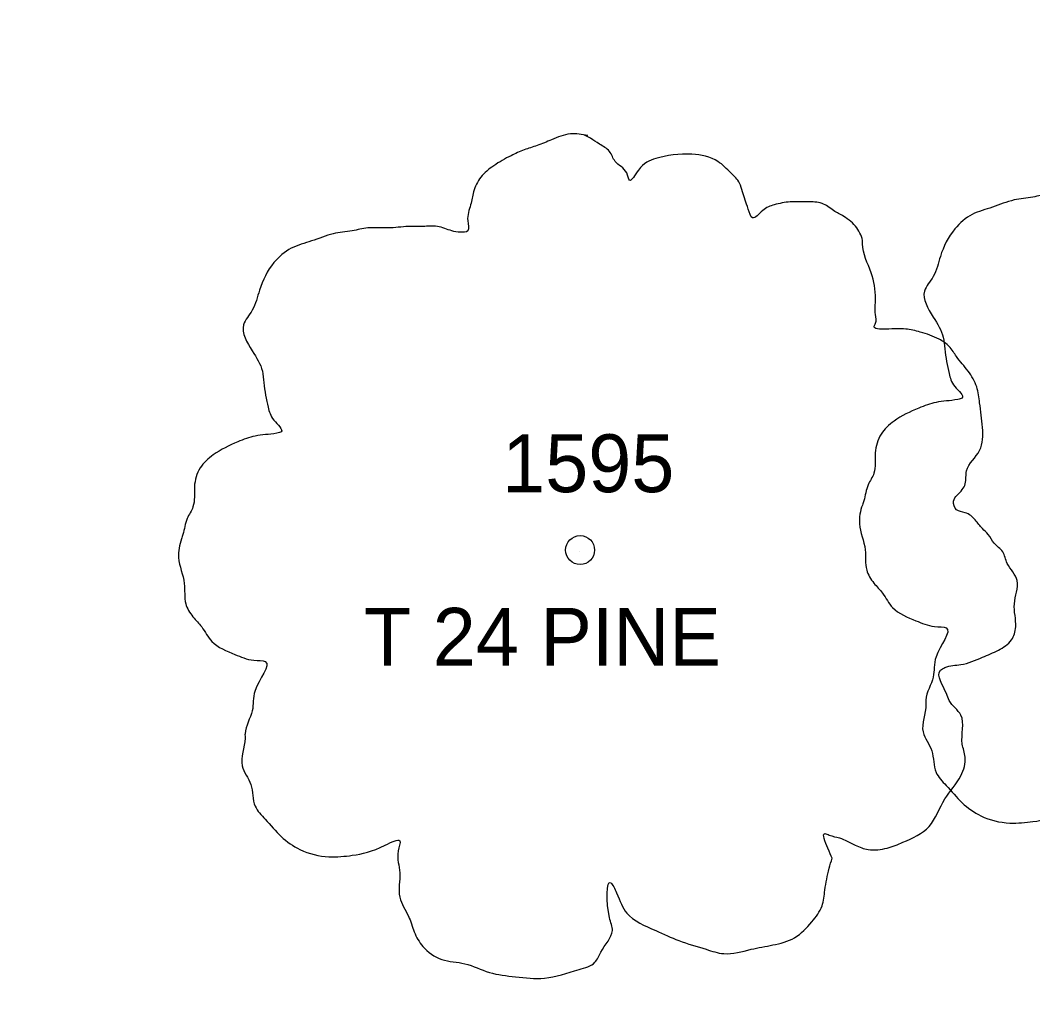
# Model space of a CAD drawing. Extents: x 1964982 to 1970452, y 1116335 to 1119906.
# Drawn here: x 1966640.09 to 1966657.58, y 1117477.19 to 1117494.07 of the extents above; entities that cross this region are included whole.
import ezdxf

# ---------------------------------------------------------------- set-up
doc = ezdxf.new("R2010")
doc.units = 0
for name, color, linetype in [('RD_EX_VEG', 7, 'Continuous'), ('RD_EX_VEG_txCode', 7, 'Continuous'), ('RD_HC_CL_Rel', 7, 'Continuous'), ('RD_HC_Data', 7, 'Continuous'), ('RD_PD_Final_TrvlWay', 7, 'Continuous')]:
    doc.layers.add(name, color=color, linetype=linetype)

msp = doc.modelspace()

# ---------------------------------------------------------------- linework, layer by layer
at = {"layer": 'RD_EX_VEG'}
for centre, radius in [((1966649.762, 1117484.912), 0.25), ((1966649.762, 1117484.912), 0.25), ((1966649.749, 1117484.893), 0.0001), ((1966649.749, 1117484.893), 0.0001)]:
    msp.add_circle(centre, radius, dxfattribs=at)
for points in [[(1966661.661, 1117492.662), (1966661.361, 1117492.687), (1966661.036, 1117492.587), (1966660.786, 1117492.487), (1966660.561, 1117492.412), (1966660.336, 1117492.312), (1966660.036, 1117492.138), (1966659.811, 1117491.938), (1966659.686, 1117491.688), (1966659.636, 1117491.463), (1966659.586, 1117491.188), (1966659.586, 1117491.013), (1966659.462, 1117490.988), (1966659.312, 1117491.013), (1966659.062, 1117491.088), (1966658.812, 1117491.088), (1966658.562, 1117491.088), (1966658.212, 1117491.063), (1966657.862, 1117491.063), (1966657.587, 1117491.013), (1966657.262, 1117490.963), (1966656.888, 1117490.838), (1966656.538, 1117490.713), (1966656.238, 1117490.463), (1966655.988, 1117489.989), (1966655.863, 1117489.639), (1966655.713, 1117489.389), (1966655.863, 1117488.939), (1966656.038, 1117488.589), (1966656.063, 1117488.389), (1966656.138, 1117487.964), (1966656.238, 1117487.74), (1966656.363, 1117487.54), (1966656.288, 1117487.515), (1966655.913, 1117487.465), (1966655.613, 1117487.365), (1966655.188, 1117487.14), (1966654.963, 1117486.915), (1966654.863, 1117486.59), (1966654.839, 1117486.24), (1966654.739, 1117486.04), (1966654.664, 1117485.765), (1966654.639, 1117485.69), (1966654.589, 1117485.366), (1966654.689, 1117484.916), (1966654.714, 1117484.566), (1966654.839, 1117484.341), (1966654.988, 1117484.166), (1966655.163, 1117483.916), (1966655.563, 1117483.691), (1966655.888, 1117483.591), (1966656.088, 1117483.566), (1966655.913, 1117483.067), (1966655.863, 1117482.717), (1966655.738, 1117482.317), (1966655.738, 1117482.242), (1966655.688, 1117481.767), (1966655.838, 1117481.442), (1966655.913, 1117481.067), (1966656.088, 1117480.843), (1966656.363, 1117480.543), (1966656.688, 1117480.318), (1966657.188, 1117480.193), (1966657.587, 1117480.218), (1966658.162, 1117480.393), (1966658.412, 1117480.468), (1966658.387, 1117480.293), (1966658.412, 1117479.918), (1966658.412, 1117479.493), (1966658.562, 1117479.168), (1966658.662, 1117478.893), (1966658.812, 1117478.643), (1966659.137, 1117478.419), (1966659.536, 1117478.344), (1966659.961, 1117478.194), (1966660.411, 1117478.119), (1966660.911, 1117478.094), (1966661.511, 1117478.244), (1966661.785, 1117478.369), (1966661.885, 1117478.544), (1966662.085, 1117478.918), (1966662.035, 1117479.143), (1966662.06, 1117479.743), (1966662.16, 1117479.568), (1966662.335, 1117479.218), (1966662.835, 1117478.918), (1966663.235, 1117478.743), (1966663.71, 1117478.593), (1966664.01, 1117478.519), (1966664.484, 1117478.593), (1966664.859, 1117478.668), (1966665.234, 1117478.793), (1966665.534, 1117479.068), (1966665.709, 1117479.343), (1966665.759, 1117479.618), (1966665.834, 1117479.993), (1966665.884, 1117480.168)], [(1966661.661, 1117492.662), (1966661.361, 1117492.687), (1966661.036, 1117492.587), (1966660.786, 1117492.487), (1966660.561, 1117492.412), (1966660.336, 1117492.312), (1966660.036, 1117492.138), (1966659.811, 1117491.938), (1966659.686, 1117491.688), (1966659.636, 1117491.463), (1966659.586, 1117491.188), (1966659.586, 1117491.013), (1966659.462, 1117490.988), (1966659.312, 1117491.013), (1966659.062, 1117491.088), (1966658.812, 1117491.088), (1966658.562, 1117491.088), (1966658.212, 1117491.063), (1966657.862, 1117491.063), (1966657.587, 1117491.013), (1966657.262, 1117490.963), (1966656.888, 1117490.838), (1966656.538, 1117490.713), (1966656.238, 1117490.463), (1966655.988, 1117489.989), (1966655.863, 1117489.639), (1966655.713, 1117489.389), (1966655.863, 1117488.939), (1966656.038, 1117488.589), (1966656.063, 1117488.389), (1966656.138, 1117487.964), (1966656.238, 1117487.74), (1966656.363, 1117487.54), (1966656.288, 1117487.515), (1966655.913, 1117487.465), (1966655.613, 1117487.365), (1966655.188, 1117487.14), (1966654.963, 1117486.915), (1966654.863, 1117486.59), (1966654.839, 1117486.24), (1966654.739, 1117486.04), (1966654.664, 1117485.765), (1966654.639, 1117485.69), (1966654.589, 1117485.366), (1966654.689, 1117484.916), (1966654.714, 1117484.566), (1966654.839, 1117484.341), (1966654.988, 1117484.166), (1966655.163, 1117483.916), (1966655.563, 1117483.691), (1966655.888, 1117483.591), (1966656.088, 1117483.566), (1966655.913, 1117483.067), (1966655.863, 1117482.717), (1966655.738, 1117482.317), (1966655.738, 1117482.242), (1966655.688, 1117481.767), (1966655.838, 1117481.442), (1966655.913, 1117481.067), (1966656.088, 1117480.843), (1966656.363, 1117480.543), (1966656.688, 1117480.318), (1966657.188, 1117480.193), (1966657.587, 1117480.218), (1966658.162, 1117480.393), (1966658.412, 1117480.468), (1966658.387, 1117480.293), (1966658.412, 1117479.918), (1966658.412, 1117479.493), (1966658.562, 1117479.168), (1966658.662, 1117478.893), (1966658.812, 1117478.643), (1966659.137, 1117478.419), (1966659.536, 1117478.344), (1966659.961, 1117478.194), (1966660.411, 1117478.119), (1966660.911, 1117478.094), (1966661.511, 1117478.244), (1966661.785, 1117478.369), (1966661.885, 1117478.544), (1966662.085, 1117478.918), (1966662.035, 1117479.143), (1966662.06, 1117479.743), (1966662.16, 1117479.568), (1966662.335, 1117479.218), (1966662.835, 1117478.918), (1966663.235, 1117478.743), (1966663.71, 1117478.593), (1966664.01, 1117478.519), (1966664.484, 1117478.593), (1966664.859, 1117478.668), (1966665.234, 1117478.793), (1966665.534, 1117479.068), (1966665.709, 1117479.343), (1966665.759, 1117479.618), (1966665.834, 1117479.993), (1966665.884, 1117480.168)], [(1966649.894, 1117492.079), (1966649.594, 1117492.104), (1966649.269, 1117492.004), (1966649.019, 1117491.904), (1966648.794, 1117491.829), (1966648.569, 1117491.729), (1966648.269, 1117491.555), (1966648.045, 1117491.355), (1966647.92, 1117491.105), (1966647.87, 1117490.88), (1966647.82, 1117490.605), (1966647.82, 1117490.43), (1966647.695, 1117490.405), (1966647.545, 1117490.43), (1966647.295, 1117490.505), (1966647.045, 1117490.505), (1966646.795, 1117490.505), (1966646.445, 1117490.48), (1966646.095, 1117490.48), (1966645.821, 1117490.43), (1966645.496, 1117490.38), (1966645.121, 1117490.255), (1966644.771, 1117490.13), (1966644.471, 1117489.88), (1966644.221, 1117489.405), (1966644.096, 1117489.056), (1966643.946, 1117488.806), (1966644.096, 1117488.356), (1966644.271, 1117488.006), (1966644.296, 1117487.806), (1966644.371, 1117487.381), (1966644.471, 1117487.156), (1966644.596, 1117486.956), (1966644.521, 1117486.932), (1966644.146, 1117486.882), (1966643.846, 1117486.782), (1966643.422, 1117486.557), (1966643.197, 1117486.332), (1966643.097, 1117486.007), (1966643.072, 1117485.657), (1966642.972, 1117485.457), (1966642.897, 1117485.182), (1966642.872, 1117485.107), (1966642.822, 1117484.782), (1966642.922, 1117484.333), (1966642.947, 1117483.983), (1966643.072, 1117483.758), (1966643.222, 1117483.583), (1966643.397, 1117483.333), (1966643.796, 1117483.108), (1966644.121, 1117483.008), (1966644.321, 1117482.983), (1966644.146, 1117482.483), (1966644.096, 1117482.134), (1966643.971, 1117481.734), (1966643.971, 1117481.659), (1966643.921, 1117481.184), (1966644.071, 1117480.859), (1966644.146, 1117480.484), (1966644.321, 1117480.259), (1966644.596, 1117479.96), (1966644.921, 1117479.735), (1966645.421, 1117479.61), (1966645.821, 1117479.635), (1966646.395, 1117479.81), (1966646.645, 1117479.885), (1966646.62, 1117479.71), (1966646.645, 1117479.335), (1966646.645, 1117478.91), (1966646.795, 1117478.585), (1966646.895, 1117478.31), (1966647.045, 1117478.06), (1966647.37, 1117477.836), (1966647.77, 1117477.761), (1966648.194, 1117477.611), (1966648.644, 1117477.536), (1966649.144, 1117477.511), (1966649.744, 1117477.661), (1966650.019, 1117477.786), (1966650.119, 1117477.96), (1966650.319, 1117478.335), (1966650.269, 1117478.56), (1966650.294, 1117479.16), (1966650.393, 1117478.985), (1966650.568, 1117478.635), (1966651.068, 1117478.335), (1966651.468, 1117478.16), (1966651.943, 1117478.01), (1966652.243, 1117477.935), (1966652.717, 1117478.01), (1966653.092, 1117478.085), (1966653.467, 1117478.21), (1966653.767, 1117478.485), (1966653.942, 1117478.76), (1966653.992, 1117479.035), (1966654.067, 1117479.41), (1966654.117, 1117479.585)], [(1966649.894, 1117492.079), (1966649.594, 1117492.104), (1966649.269, 1117492.004), (1966649.019, 1117491.904), (1966648.794, 1117491.829), (1966648.569, 1117491.729), (1966648.269, 1117491.555), (1966648.045, 1117491.355), (1966647.92, 1117491.105), (1966647.87, 1117490.88), (1966647.82, 1117490.605), (1966647.82, 1117490.43), (1966647.695, 1117490.405), (1966647.545, 1117490.43), (1966647.295, 1117490.505), (1966647.045, 1117490.505), (1966646.795, 1117490.505), (1966646.445, 1117490.48), (1966646.095, 1117490.48), (1966645.821, 1117490.43), (1966645.496, 1117490.38), (1966645.121, 1117490.255), (1966644.771, 1117490.13), (1966644.471, 1117489.88), (1966644.221, 1117489.405), (1966644.096, 1117489.056), (1966643.946, 1117488.806), (1966644.096, 1117488.356), (1966644.271, 1117488.006), (1966644.296, 1117487.806), (1966644.371, 1117487.381), (1966644.471, 1117487.156), (1966644.596, 1117486.956), (1966644.521, 1117486.932), (1966644.146, 1117486.882), (1966643.846, 1117486.782), (1966643.422, 1117486.557), (1966643.197, 1117486.332), (1966643.097, 1117486.007), (1966643.072, 1117485.657), (1966642.972, 1117485.457), (1966642.897, 1117485.182), (1966642.872, 1117485.107), (1966642.822, 1117484.782), (1966642.922, 1117484.333), (1966642.947, 1117483.983), (1966643.072, 1117483.758), (1966643.222, 1117483.583), (1966643.397, 1117483.333), (1966643.796, 1117483.108), (1966644.121, 1117483.008), (1966644.321, 1117482.983), (1966644.146, 1117482.483), (1966644.096, 1117482.134), (1966643.971, 1117481.734), (1966643.971, 1117481.659), (1966643.921, 1117481.184), (1966644.071, 1117480.859), (1966644.146, 1117480.484), (1966644.321, 1117480.259), (1966644.596, 1117479.96), (1966644.921, 1117479.735), (1966645.421, 1117479.61), (1966645.821, 1117479.635), (1966646.395, 1117479.81), (1966646.645, 1117479.885), (1966646.62, 1117479.71), (1966646.645, 1117479.335), (1966646.645, 1117478.91), (1966646.795, 1117478.585), (1966646.895, 1117478.31), (1966647.045, 1117478.06), (1966647.37, 1117477.836), (1966647.77, 1117477.761), (1966648.194, 1117477.611), (1966648.644, 1117477.536), (1966649.144, 1117477.511), (1966649.744, 1117477.661), (1966650.019, 1117477.786), (1966650.119, 1117477.96), (1966650.319, 1117478.335), (1966650.269, 1117478.56), (1966650.294, 1117479.16), (1966650.393, 1117478.985), (1966650.568, 1117478.635), (1966651.068, 1117478.335), (1966651.468, 1117478.16), (1966651.943, 1117478.01), (1966652.243, 1117477.935), (1966652.717, 1117478.01), (1966653.092, 1117478.085), (1966653.467, 1117478.21), (1966653.767, 1117478.485), (1966653.942, 1117478.76), (1966653.992, 1117479.035), (1966654.067, 1117479.41), (1966654.117, 1117479.585)], [(1966654.117, 1117479.585), (1966654.042, 1117479.76), (1966653.992, 1117480.01), (1966654.067, 1117479.985), (1966654.242, 1117479.935), (1966654.517, 1117479.81), (1966654.742, 1117479.735), (1966655.066, 1117479.76), (1966655.341, 1117479.86), (1966655.791, 1117480.135), (1966656.066, 1117480.609), (1966656.341, 1117481.009), (1966656.416, 1117481.334), (1966656.366, 1117481.559), (1966656.341, 1117482.059), (1966656.141, 1117482.309), (1966656.091, 1117482.433), (1966655.991, 1117482.833), (1966656.066, 1117482.883), (1966656.341, 1117482.933), (1966656.716, 1117483.058), (1966656.991, 1117483.183), (1966657.216, 1117483.358), (1966657.29, 1117483.583), (1966657.266, 1117483.983), (1966657.315, 1117484.383), (1966657.241, 1117484.533), (1966657.141, 1117484.682), (1966657.066, 1117484.882), (1966656.916, 1117485.032), (1966656.816, 1117485.182), (1966656.716, 1117485.282), (1966656.591, 1117485.432), (1966656.416, 1117485.557), (1966656.266, 1117485.607), (1966656.216, 1117485.757), (1966656.366, 1117485.957), (1966656.416, 1117486.057), (1966656.441, 1117486.282), (1966656.666, 1117486.632), (1966656.716, 1117487.031), (1966656.666, 1117487.456), (1966656.616, 1117487.731), (1966656.466, 1117488.006), (1966656.266, 1117488.256), (1966656.141, 1117488.431), (1966655.966, 1117488.556), (1966655.641, 1117488.681), (1966655.391, 1117488.731), (1966655.041, 1117488.731), (1966654.842, 1117488.781), (1966654.867, 1117488.831), (1966654.867, 1117488.981), (1966654.867, 1117489.256), (1966654.792, 1117489.705), (1966654.642, 1117490.205), (1966654.642, 1117490.23), (1966654.542, 1117490.48), (1966654.317, 1117490.68), (1966654.142, 1117490.78), (1966653.942, 1117490.905), (1966653.692, 1117490.93), (1966653.392, 1117490.93), (1966653.117, 1117490.88), (1966652.917, 1117490.78), (1966652.742, 1117490.655), (1966652.667, 1117490.805), (1966652.568, 1117491.105), (1966652.518, 1117491.255), (1966652.368, 1117491.43), (1966652.143, 1117491.629), (1966651.693, 1117491.754), (1966651.068, 1117491.679), (1966650.768, 1117491.48), (1966650.618, 1117491.305), (1966650.568, 1117491.43), (1966650.368, 1117491.629), (1966650.269, 1117491.804), (1966650.094, 1117491.929), (1966649.944, 1117492.029), (1966649.844, 1117492.079)], [(1966654.117, 1117479.585), (1966654.042, 1117479.76), (1966653.992, 1117480.01), (1966654.067, 1117479.985), (1966654.242, 1117479.935), (1966654.517, 1117479.81), (1966654.742, 1117479.735), (1966655.066, 1117479.76), (1966655.341, 1117479.86), (1966655.791, 1117480.135), (1966656.066, 1117480.609), (1966656.341, 1117481.009), (1966656.416, 1117481.334), (1966656.366, 1117481.559), (1966656.341, 1117482.059), (1966656.141, 1117482.309), (1966656.091, 1117482.433), (1966655.991, 1117482.833), (1966656.066, 1117482.883), (1966656.341, 1117482.933), (1966656.716, 1117483.058), (1966656.991, 1117483.183), (1966657.216, 1117483.358), (1966657.29, 1117483.583), (1966657.266, 1117483.983), (1966657.315, 1117484.383), (1966657.241, 1117484.533), (1966657.141, 1117484.682), (1966657.066, 1117484.882), (1966656.916, 1117485.032), (1966656.816, 1117485.182), (1966656.716, 1117485.282), (1966656.591, 1117485.432), (1966656.416, 1117485.557), (1966656.266, 1117485.607), (1966656.216, 1117485.757), (1966656.366, 1117485.957), (1966656.416, 1117486.057), (1966656.441, 1117486.282), (1966656.666, 1117486.632), (1966656.716, 1117487.031), (1966656.666, 1117487.456), (1966656.616, 1117487.731), (1966656.466, 1117488.006), (1966656.266, 1117488.256), (1966656.141, 1117488.431), (1966655.966, 1117488.556), (1966655.641, 1117488.681), (1966655.391, 1117488.731), (1966655.041, 1117488.731), (1966654.842, 1117488.781), (1966654.867, 1117488.831), (1966654.867, 1117488.981), (1966654.867, 1117489.256), (1966654.792, 1117489.705), (1966654.642, 1117490.205), (1966654.642, 1117490.23), (1966654.542, 1117490.48), (1966654.317, 1117490.68), (1966654.142, 1117490.78), (1966653.942, 1117490.905), (1966653.692, 1117490.93), (1966653.392, 1117490.93), (1966653.117, 1117490.88), (1966652.917, 1117490.78), (1966652.742, 1117490.655), (1966652.667, 1117490.805), (1966652.568, 1117491.105), (1966652.518, 1117491.255), (1966652.368, 1117491.43), (1966652.143, 1117491.629), (1966651.693, 1117491.754), (1966651.068, 1117491.679), (1966650.768, 1117491.48), (1966650.618, 1117491.305), (1966650.568, 1117491.43), (1966650.368, 1117491.629), (1966650.269, 1117491.804), (1966650.094, 1117491.929), (1966649.944, 1117492.029), (1966649.844, 1117492.079)]]:
    msp.add_spline(points, degree=3, dxfattribs=at)
at = {"layer": 'RD_HC_CL_Rel'}
msp.add_arc((1966373.74, 1118527.456), 1145.915, 281.904723, 295.046328, dxfattribs=at)
at = {"layer": 'RD_PD_Final_TrvlWay'}
for radius in [1134.915, 1156.915]:
    msp.add_arc((1966373.74, 1118527.456), radius, 281.904723, 295.046328, dxfattribs=at)

# ---------------------------------------------------------------- texts
at = {"layer": 'RD_EX_VEG_txCode'}
for s, p in [('1595', (1966648.415, 1117485.912)), ('1595', (1966648.415, 1117485.912)), ('T 24 PINE', (1966646.026, 1117482.912)), ('T 24 PINE', (1966646.026, 1117482.912))]:
    msp.add_text(s, height=1, dxfattribs=at).set_placement(p)
at = {"layer": 'RD_HC_Data'}
msp.add_text('PC=49+10.12', height=6, rotation=101.9047, dxfattribs=at).set_placement((1966669.912, 1117486.752))

doc.saveas('drawing.dxf')
